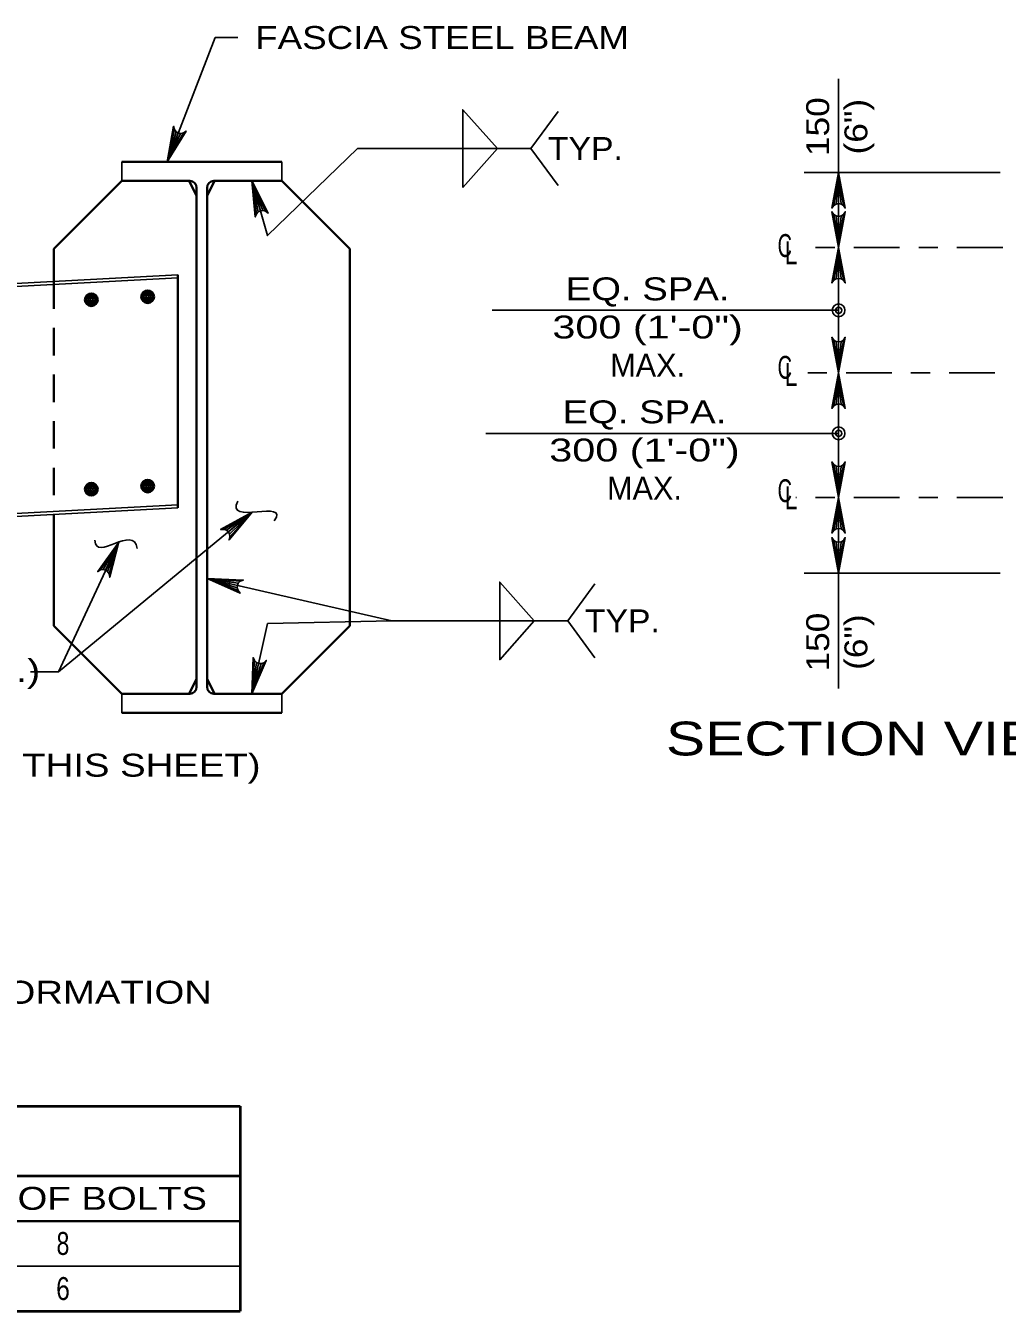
# Model space of a CAD drawing. Extents: x -11 to 79, y -154 to 0.
# Drawn here: x 51.83 to 56.98, y -59.49 to -52.75 of the extents above; entities that cross this region are included whole.
import ezdxf
from ezdxf.enums import TextEntityAlignment as Align

# ---------------------------------------------------------------- set-up
doc = ezdxf.new("R2010")
doc.units = 0
doc.header["$LTSCALE"] = 0.048
doc.linetypes.add('DOT_DASHED', pattern=[7.7, 5, -1.2, 0.3, -1.2])
doc.linetypes.add('MEDIUM_DASHED', pattern=[4.5, 3, -1.5])
for name, color, linetype, lineweight in [('2', 7, 'Continuous', 35), ('3', 7, 'Continuous', 25), ('4', 7, 'Continuous', 25), ('5', 7, 'Continuous', 25)]:
    doc.layers.add(name, color=color, linetype=linetype, lineweight=lineweight)

msp = doc.modelspace()

# ---------------------------------------------------------------- hatches: boundary and pattern name
at = {"layer": '3'}
for points in [[(52.63625, -53.36183), (52.59892, -53.34742), (52.57433, -53.46658)], [(56.07175, -53.64267), (56.11175, -53.64267), (56.09175, -53.52267)], [(53.0325, -53.68742), (53.07092, -53.67625), (53.01833, -53.56658)], [(56.07175, -53.79442), (56.11175, -53.79442), (56.09175, -53.91442)], [(56.07175, -54.03442), (56.11175, -54.03442), (56.09175, -53.91442)], [(56.07175, -54.45192), (56.11175, -54.45192), (56.09175, -54.57192)], [(56.07175, -54.69192), (56.11175, -54.69192), (56.09175, -54.57192)], [(56.07175, -55.1045), (56.11175, -55.1045), (56.09175, -55.2245)], [(56.07175, -55.3445), (56.11175, -55.3445), (56.09175, -55.2245)], [(56.07175, -55.50108), (56.11175, -55.50108), (56.09175, -55.62108)], [(52.89658, -55.69575), (52.9055, -55.65675), (52.78408, -55.6495)], [(53.06425, -56.13975), (53.02517, -56.13092), (53.01833, -56.25242)]]:
    msp.add_hatch(color=256, dxfattribs=at).paths.add_polyline_path(points)

# ---------------------------------------------------------------- linework, layer by layer
at = {"layer": '2', "lineweight": 25}
for points in [[(52.57433, -53.46658), (52.60892, -53.28008), (52.613, -53.29708), (52.622, -53.3085), (52.63292, -53.315), (52.64533, -53.3175), (52.65967, -53.31508), (52.67408, -53.30525), (52.57433, -53.46658), (52.65967, -53.31508), (52.64533, -53.3175), (52.57433, -53.46658), (52.63292, -53.315), (52.622, -53.3085), (52.57433, -53.46658), (52.613, -53.29708)], [(53.01842, -53.56658), (53.10383, -53.73592), (53.09025, -53.72492), (53.07617, -53.72125), (53.06358, -53.72267), (53.05217, -53.72825), (53.04225, -53.73883), (53.03667, -53.75533), (53.01842, -53.56658), (53.04225, -53.73883), (53.05217, -53.72825), (53.01842, -53.56658), (53.06358, -53.72267), (53.07617, -53.72125), (53.01842, -53.56658), (53.09025, -53.72492)], [(53.02092, -55.30142), (52.89925, -55.44692), (52.904, -55.43008), (52.90175, -55.41575), (52.8955, -55.40475), (52.88592, -55.39642), (52.87225, -55.3915), (52.85483, -55.39292), (53.02092, -55.30142), (52.87225, -55.3915), (52.88592, -55.39642), (53.02092, -55.30142), (52.8955, -55.40475), (52.90175, -55.41575), (53.02092, -55.30142), (52.904, -55.43008)], [(52.32117, -55.45817), (52.2745, -55.642), (52.2715, -55.62475), (52.26325, -55.61283), (52.25283, -55.60558), (52.24058, -55.60225), (52.22608, -55.60375), (52.21108, -55.61258), (52.32117, -55.45817), (52.22608, -55.60375), (52.24058, -55.60225), (52.32117, -55.45817), (52.25283, -55.60558), (52.26325, -55.61283), (52.32117, -55.45817), (52.2715, -55.62475)], [(52.78408, -55.6495), (52.97358, -55.657), (52.95742, -55.6635), (52.94733, -55.674), (52.9425, -55.68575), (52.94183, -55.69842), (52.94625, -55.71225), (52.958, -55.72517), (52.78408, -55.6495), (52.94625, -55.71225), (52.94183, -55.69842), (52.78408, -55.6495), (52.9425, -55.68575), (52.94733, -55.674), (52.78408, -55.6495), (52.95742, -55.6635)], [(53.01842, -56.25242), (53.02525, -56.06292), (53.03183, -56.07908), (53.04242, -56.08908), (53.05408, -56.09392), (53.06675, -56.0945), (53.08058, -56.09008), (53.0935, -56.07825), (53.01842, -56.25242), (53.08058, -56.09008), (53.06675, -56.0945), (53.01842, -56.25242), (53.05408, -56.09392), (53.04242, -56.08908), (53.01842, -56.25242), (53.03183, -56.07908)]]:
    msp.add_lwpolyline(points, dxfattribs=at)
at = {"layer": '3'}
for p, q in [((52.57433, -53.46658), (52.82592, -52.81525)), ((52.82592, -52.81525), (52.94592, -52.81525)), ((56.09175, -53.91442), (56.09175, -53.031)), ((54.4795, -53.39675), (54.62208, -53.20317)), ((53.57142, -53.39675), (54.4795, -53.39675)), ((54.12292, -53.60008), (54.30442, -53.39675)), ((54.12292, -53.39675), (54.12292, -53.60008)), ((54.4795, -53.39675), (54.62208, -53.59025)), ((56.93817, -53.52267), (55.91175, -53.52267)), ((56.09175, -53.91442), (56.09175, -56.22458)), ((56.09175, -54.24417), (54.27675, -54.24417)), ((56.09175, -54.8885), (54.24367, -54.8885)), ((53.02092, -55.30142), (52.00642, -56.137)), ((52.32117, -55.45817), (52.00642, -56.137)), ((52.78408, -55.6495), (53.75108, -55.87067)), ((54.67308, -55.87067), (54.81567, -55.67708)), ((56.93817, -55.62108), (55.91175, -55.62108)), ((53.01842, -56.25242), (53.10125, -55.8845)), ((53.10125, -55.8845), (53.75108, -55.87067)), ((53.75108, -55.87067), (54.67308, -55.87067)), ((54.67308, -55.87067), (54.81567, -56.06425)), ((52.00642, -56.137), (51.85975, -56.137)), ((46.19175, -59.25067), (52.95675, -59.25067))]:
    msp.add_line(p, q, dxfattribs=at)
at = {"layer": '3', "linetype": 'DOT_DASHED'}
msp.add_line((56.91067, -54.57192), (55.86175, -54.57192), dxfattribs=at)
at = {"layer": '3', "lineweight": 40}
for p, q in [((46.19175, -58.41233), (52.95675, -58.41233)), ((52.95675, -58.41233), (52.95675, -59.48692)), ((46.19175, -58.77825), (52.95675, -58.77825)), ((46.19175, -59.48692), (52.95675, -59.48692))]:
    msp.add_line(p, q, dxfattribs=at)
at = {"layer": '3', "lineweight": 35}
msp.add_line((46.19175, -59.0145), (52.95675, -59.0145), dxfattribs=at)
at = {"layer": '3'}
for points in [[(54.12292, -53.39675), (54.12292, -53.19333), (54.30442, -53.39675)], [(53.01842, -53.56658), (53.10125, -53.85283), (53.57142, -53.39675)], [(56.09175, -53.52267), (56.12667, -53.70908), (56.11675, -53.69475), (56.10425, -53.68733), (56.09175, -53.68517), (56.07925, -53.68733), (56.06675, -53.69475), (56.05683, -53.70908), (56.09175, -53.52267), (56.06675, -53.69475), (56.07925, -53.68733), (56.09175, -53.52267), (56.09175, -53.68517), (56.10425, -53.68733), (56.09175, -53.52267), (56.11675, -53.69475)], [(56.09175, -53.91442), (56.05683, -53.728), (56.06675, -53.74233), (56.07925, -53.74975), (56.09175, -53.75192), (56.10425, -53.74975), (56.11675, -53.74233), (56.12667, -53.728), (56.09175, -53.91442), (56.11675, -53.74233), (56.10425, -53.74975), (56.09175, -53.91442), (56.09175, -53.75192), (56.07925, -53.74975), (56.09175, -53.91442), (56.06675, -53.74233)], [(56.09175, -53.91442), (56.12667, -54.10083), (56.11675, -54.0865), (56.10425, -54.07908), (56.09175, -54.07692), (56.07925, -54.07908), (56.06675, -54.0865), (56.05683, -54.10083), (56.09175, -53.91442), (56.06675, -54.0865), (56.07925, -54.07908), (56.09175, -53.91442), (56.09175, -54.07692), (56.10425, -54.07908), (56.09175, -53.91442), (56.11675, -54.0865)], [(56.09175, -54.57192), (56.12667, -54.3855), (56.11675, -54.39983), (56.10425, -54.40725), (56.09175, -54.40942), (56.07925, -54.40725), (56.06675, -54.39983), (56.05683, -54.3855), (56.09175, -54.57192), (56.06675, -54.39983), (56.07925, -54.40725), (56.09175, -54.57192), (56.09175, -54.40942), (56.10425, -54.40725), (56.09175, -54.57192), (56.11675, -54.39983)], [(56.09175, -54.57192), (56.12667, -54.75833), (56.11675, -54.744), (56.10425, -54.73658), (56.09175, -54.73442), (56.07925, -54.73658), (56.06675, -54.744), (56.05683, -54.75833), (56.09175, -54.57192), (56.06675, -54.744), (56.07925, -54.73658), (56.09175, -54.57192), (56.09175, -54.73442), (56.10425, -54.73658), (56.09175, -54.57192), (56.11675, -54.744)], [(56.09175, -55.2245), (56.12667, -55.03808), (56.11675, -55.05242), (56.10425, -55.05983), (56.09175, -55.062), (56.07925, -55.05983), (56.06675, -55.05242), (56.05683, -55.03808), (56.09175, -55.2245), (56.06675, -55.05242), (56.07925, -55.05983), (56.09175, -55.2245), (56.09175, -55.062), (56.10425, -55.05983), (56.09175, -55.2245), (56.11675, -55.05242)], [(56.09175, -55.2245), (56.12667, -55.41092), (56.11675, -55.39658), (56.10425, -55.38917), (56.09175, -55.387), (56.07925, -55.38917), (56.06675, -55.39658), (56.05683, -55.41092), (56.09175, -55.2245), (56.06675, -55.39658), (56.07925, -55.38917), (56.09175, -55.2245), (56.09175, -55.387), (56.10425, -55.38917), (56.09175, -55.2245), (56.11675, -55.39658)], [(56.09175, -55.62108), (56.05683, -55.43467), (56.06675, -55.449), (56.07925, -55.45642), (56.09175, -55.45858), (56.10425, -55.45642), (56.11675, -55.449), (56.12667, -55.43467), (56.09175, -55.62108), (56.11675, -55.449), (56.10425, -55.45642), (56.09175, -55.62108), (56.09175, -55.45858), (56.07925, -55.45642), (56.09175, -55.62108), (56.06675, -55.449)], [(54.3165, -55.87067), (54.3165, -55.66725), (54.498, -55.87067)], [(54.3165, -55.87067), (54.3165, -56.074), (54.498, -55.87067)]]:
    msp.add_lwpolyline(points, dxfattribs=at)
for points in [[(52.63625, -53.36183), (52.59892, -53.34742), (52.57433, -53.46658)], [(56.07175, -53.64267), (56.11175, -53.64267), (56.09175, -53.52267)], [(53.0325, -53.68742), (53.07092, -53.67625), (53.01833, -53.56658)], [(56.07175, -53.79442), (56.11175, -53.79442), (56.09175, -53.91442)], [(56.07175, -54.03442), (56.11175, -54.03442), (56.09175, -53.91442)], [(56.07175, -54.45192), (56.11175, -54.45192), (56.09175, -54.57192)], [(56.07175, -54.69192), (56.11175, -54.69192), (56.09175, -54.57192)], [(56.07175, -55.1045), (56.11175, -55.1045), (56.09175, -55.2245)], [(56.07175, -55.3445), (56.11175, -55.3445), (56.09175, -55.2245)], [(56.07175, -55.50108), (56.11175, -55.50108), (56.09175, -55.62108)], [(52.89658, -55.69575), (52.9055, -55.65675), (52.78408, -55.6495)], [(53.06425, -56.13975), (53.02517, -56.13092), (53.01833, -56.25242)]]:
    msp.add_lwpolyline(points, close=True, dxfattribs=at)
for centre, radius in [((56.09175, -54.24416), 0.03333), ((56.09175, -54.24416), 0.01667), ((56.09175, -54.88849), 0.03333), ((56.09175, -54.88849), 0.01667)]:
    msp.add_circle(centre, radius, dxfattribs=at)
for points in [[(52.94483, -55.24333), (52.8715, -55.37517), (53.22342, -55.22867), (53.1355, -55.34592)], [(52.197, -55.44842), (52.197, -55.56567), (52.40233, -55.3605), (52.417, -55.49242)]]:
    msp.add_open_spline(points, degree=3, dxfattribs=at)
at = {"layer": '4', "lineweight": 35}
for p, q in [((53.17575, -53.46658), (52.33717, -53.46658)), ((52.33717, -53.56658), (51.98092, -53.92283)), ((52.69333, -53.56658), (52.33717, -53.56658)), ((52.68958, -53.56658), (52.72892, -53.64533)), ((52.82342, -53.56658), (52.78408, -53.64533)), ((53.17575, -53.56658), (52.81958, -53.56658)), ((53.17575, -53.56658), (53.53208, -53.92283)), ((52.72892, -53.60217), (52.72892, -56.21683)), ((52.78408, -53.60217), (52.78408, -56.21683)), ((51.98092, -53.92283), (51.98092, -54.09258)), ((53.53208, -53.92283), (53.53208, -55.89608)), ((52.6305, -54.05867), (52.6305, -55.27917)), ((51.98092, -55.313), (51.98092, -55.89608)), ((51.98092, -55.89608), (52.33717, -56.25242)), ((53.17575, -56.25242), (53.53208, -55.89608)), ((52.68958, -56.25242), (52.72892, -56.17367)), ((52.82342, -56.25242), (52.78408, -56.17367)), ((52.69333, -56.25242), (52.33717, -56.25242)), ((53.17575, -56.25242), (52.81958, -56.25242)), ((53.17575, -56.35242), (52.33717, -56.35242))]:
    msp.add_line(p, q, dxfattribs=at)
at = {"layer": '4', "linetype": 'DOT_DASHED'}
for p, q in [((56.95133, -53.91442), (55.87825, -53.91442)), ((56.95133, -55.2245), (55.86725, -55.2245))]:
    msp.add_line(p, q, dxfattribs=at)
at = {"layer": '4', "linetype": 'MEDIUM_DASHED', "lineweight": 35}
msp.add_line((51.98092, -54.09258), (51.98092, -55.313), dxfattribs=at)
at = {"layer": '4', "lineweight": 35}
for centre, radius in [((52.17771, -54.18883), 0.03333), ((52.17771, -54.18883), 0.025), ((52.17771, -54.18883), 0.01667), ((52.17771, -54.18883), 0.00833), ((52.47298, -54.17286), 0.03333), ((52.47298, -54.17286), 0.025), ((52.47298, -54.17286), 0.01667), ((52.47298, -54.17286), 0.00833), ((52.47298, -55.16498), 0.03333), ((52.47298, -55.16498), 0.025), ((52.17771, -55.18095), 0.03333), ((52.17771, -55.18095), 0.025), ((52.17771, -55.18095), 0.01667), ((52.17771, -55.18095), 0.00833), ((52.47298, -55.16498), 0.01667), ((52.47298, -55.16498), 0.00833)]:
    msp.add_circle(centre, radius, dxfattribs=at)
for centre, start, end in [((52.69331, -53.60213), 0, 90), ((52.81958, -53.60213), 90, 180), ((52.69331, -56.2168), 270, 0), ((52.81958, -56.2168), 180, 270)]:
    msp.add_arc(centre, 0.03558, start, end, dxfattribs=at)
at = {"layer": '5'}
for p, q in [((52.33717, -53.46658), (52.33717, -53.56658)), ((53.17575, -53.46658), (53.17575, -53.56658)), ((52.6305, -54.05867), (50.47283, -54.17125)), ((52.6305, -54.07442), (50.47283, -54.18692)), ((52.6305, -55.27917), (50.47067, -55.39183)), ((52.6305, -55.26342), (50.47075, -55.376)), ((52.33717, -56.35242), (52.33717, -56.25242)), ((53.17575, -56.35242), (53.17575, -56.25242))]:
    msp.add_line(p, q, dxfattribs=at)

# ---------------------------------------------------------------- texts
at = {"layer": '3'}
for s, width, p in [('FASCIA STEEL BEAM', 1.2, (53.03583, -52.87525)), ('TYP.', 1.1, (54.56942, -53.45675)), ('C', 0.65, (55.772, -53.96483)), ('L', 0.75, (55.80975, -54.0025)), ('C', 0.65, (55.772, -54.60275)), ('L', 0.75, (55.80975, -54.64042)), ('C', 0.65, (55.772, -55.24892)), ('L', 0.75, (55.80975, -55.28667)), ('TYP.', 1.1, (54.763, -55.93075)), ('BEARING STIFFENER (TYP.)', 1.3, (49.09417, -56.19108)), ('CHANNEL (SEE TABLE-1 THIS SHEET)', 1.25, (49.40833, -56.68667))]:
    msp.add_text(s, height=0.12, dxfattribs=dict(at, width=width)).set_placement(p)
at = {"layer": '3', "width": 1.15}
for s, p in [('150', (56.04217, -53.28229)), ('(6")', (56.24217, -53.28221)), ('150', (56.04217, -55.98196)), ('(6")', (56.24217, -55.98187))]:
    msp.add_text(s, height=0.12, rotation=90, dxfattribs=at).set_placement(p, align=Align.CENTER)
at = {"layer": '3'}
for s, height, width, p in [('EQ. SPA.', 0.12, 1.25, (55.09121, -54.19167)), ('300 (1\'-0")', 0.12, 1.35, (55.09129, -54.39167)), ('EQ. SPA.', 0.12, 1.25, (55.07462, -54.836)), ('300 (1\'-0")', 0.12, 1.35, (55.07471, -55.036)), ('SECTION VIEW- END P DETAIL', 0.1772, 1.3, (57.455, -56.57558)), ('REFER TO BC-754M FOR ADDITIONAL INFORMATION', 0.12, 1.25, (50.25187, -57.87575)), ('NO. OF BOLTS', 0.12, 1.25, (52.08125, -58.95533)), ('8', 0.12, 0.75, (52.02921, -59.19158)), ('6', 0.12, 0.8, (52.02942, -59.42775))]:
    msp.add_text(s, height=height, dxfattribs=dict(at, width=width)).set_placement(p, align=Align.CENTER)
for p in [(55.09129, -54.59167), (55.07471, -55.236)]:
    msp.add_text('MAX.', height=0.12, dxfattribs=at).set_placement(p, align=Align.CENTER)

doc.saveas('drawing.dxf')
